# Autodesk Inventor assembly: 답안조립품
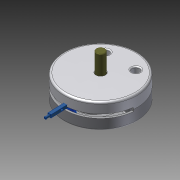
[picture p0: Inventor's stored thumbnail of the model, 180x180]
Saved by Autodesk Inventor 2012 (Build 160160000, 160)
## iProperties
Created: 2015-04
Part Number: 답안조립품
Document SubType Name: Assembly
Designer: Owner
Author: Owner
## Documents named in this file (9)
- C:\Documents and Settings\Owner\바탕 화면\450405V1007\답안조립품.iam
- C:\Documents and Settings\Owner\바탕 화면\450405V1007\1 본체.ipt
- C:\Documents and Settings\Owner\바탕 화면\450405V1007\베어링62_22.ipt
- C:\Documents and Settings\Owner\바탕 화면\450405V1007\덮개.ipt
- C:\Documents and Settings\Owner\바탕 화면\450405V1007\축.ipt
- C:\Documents and Settings\Owner\바탕 화면\450405V1007\멈춤링.ipt
- C:\Documents and Settings\Owner\바탕 화면\450405V1007\평행핀.ipt
- C:\Documents and Settings\Owner\바탕 화면\450405V1007\슬라이더2.ipt
- C:\Documents and Settings\Owner\바탕 화면\450405V1007\슬라이더.ipt
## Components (1 placed, 1 different names)
1. 1 본체:1
